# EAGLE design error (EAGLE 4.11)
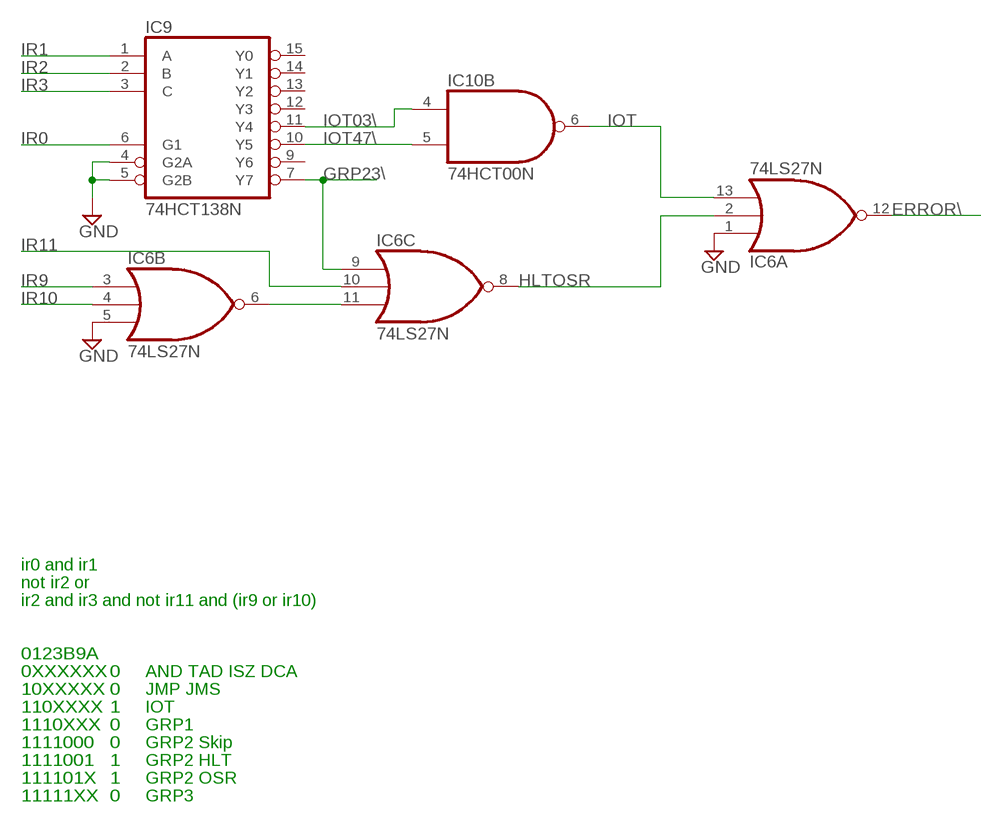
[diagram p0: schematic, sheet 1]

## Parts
IC6  74LS27N  [DIL14]
IC9  74HCT138N  [DIL16]
IC10  74HCT00N  [DIL14]

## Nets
ERROR\: IC6.12(A:O)
GND: IC6.1(A:I0) IC6.5(B:I2) IC9.4(G2A) IC9.5(G2B)
GRP23\: IC6.9(C:I0) IC9.7(Y7)
HLTOSR: IC6.2(A:I1) IC6.8(C:O)
IOT: IC6.13(A:I2) IC10.6(B:O)
IOT03\: IC9.11(Y4) IC10.4(B:I0)
IOT47\: IC9.10(Y5) IC10.5(B:I1)
IR0: IC9.6(G1)
IR1: IC9.1(A)
IR2: IC9.2(B)
IR3: IC9.3(C)
IR9: IC6.3(B:I0)
IR10: IC6.4(B:I1)
IR11: IC6.10(C:I1)
N$14: IC6.6(B:O) IC6.11(C:I2)
Unconnected: IC9.9(Y6) IC9.12(Y3) IC9.13(Y2) IC9.14(Y1) IC9.15(Y0) IC10.1(A:I0) IC10.2(A:I1) IC10.3(A:O) IC10.8(C:O) IC10.9(C:I0) IC10.10(C:I1) IC10.11(D:O) IC10.12(D:I0) IC10.13(D:I1)

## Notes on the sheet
- ir0 and ir1
- not ir2 or
- ir2 and ir3 and not ir11 and (ir9 or ir10)
- 0123B9A
- 0XXXXXX | 0 | AND TAD ISZ DCA
- 10XXXXX | 0 | JMP JMS
- 110XXXX | 1 | IOT
- 1110XXX | 0 | GRP1
- 1111000 | 0 | GRP2 Skip
- 1111001 | 1 | GRP2 HLT
- 111101X | 1 | GRP2 OSR
- 11111XX | 0 | GRP3

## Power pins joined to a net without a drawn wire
GND: IC6.7(P:GND) IC9.8(GND) IC10.7(P:GND)
VCC: IC6.14(P:VCC) IC9.16(VCC) IC10.14(P:VCC)

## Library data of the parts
IC6 = 74xx-jameco:74*27: Triple 3-input NOR gate
IC9 = 74xx-jameco:74*138: 3-line to 8-line DECODER/DEMULTIPLEXER
IC10 = 74xx-jameco:74*00: Quad 2-input NAND gate

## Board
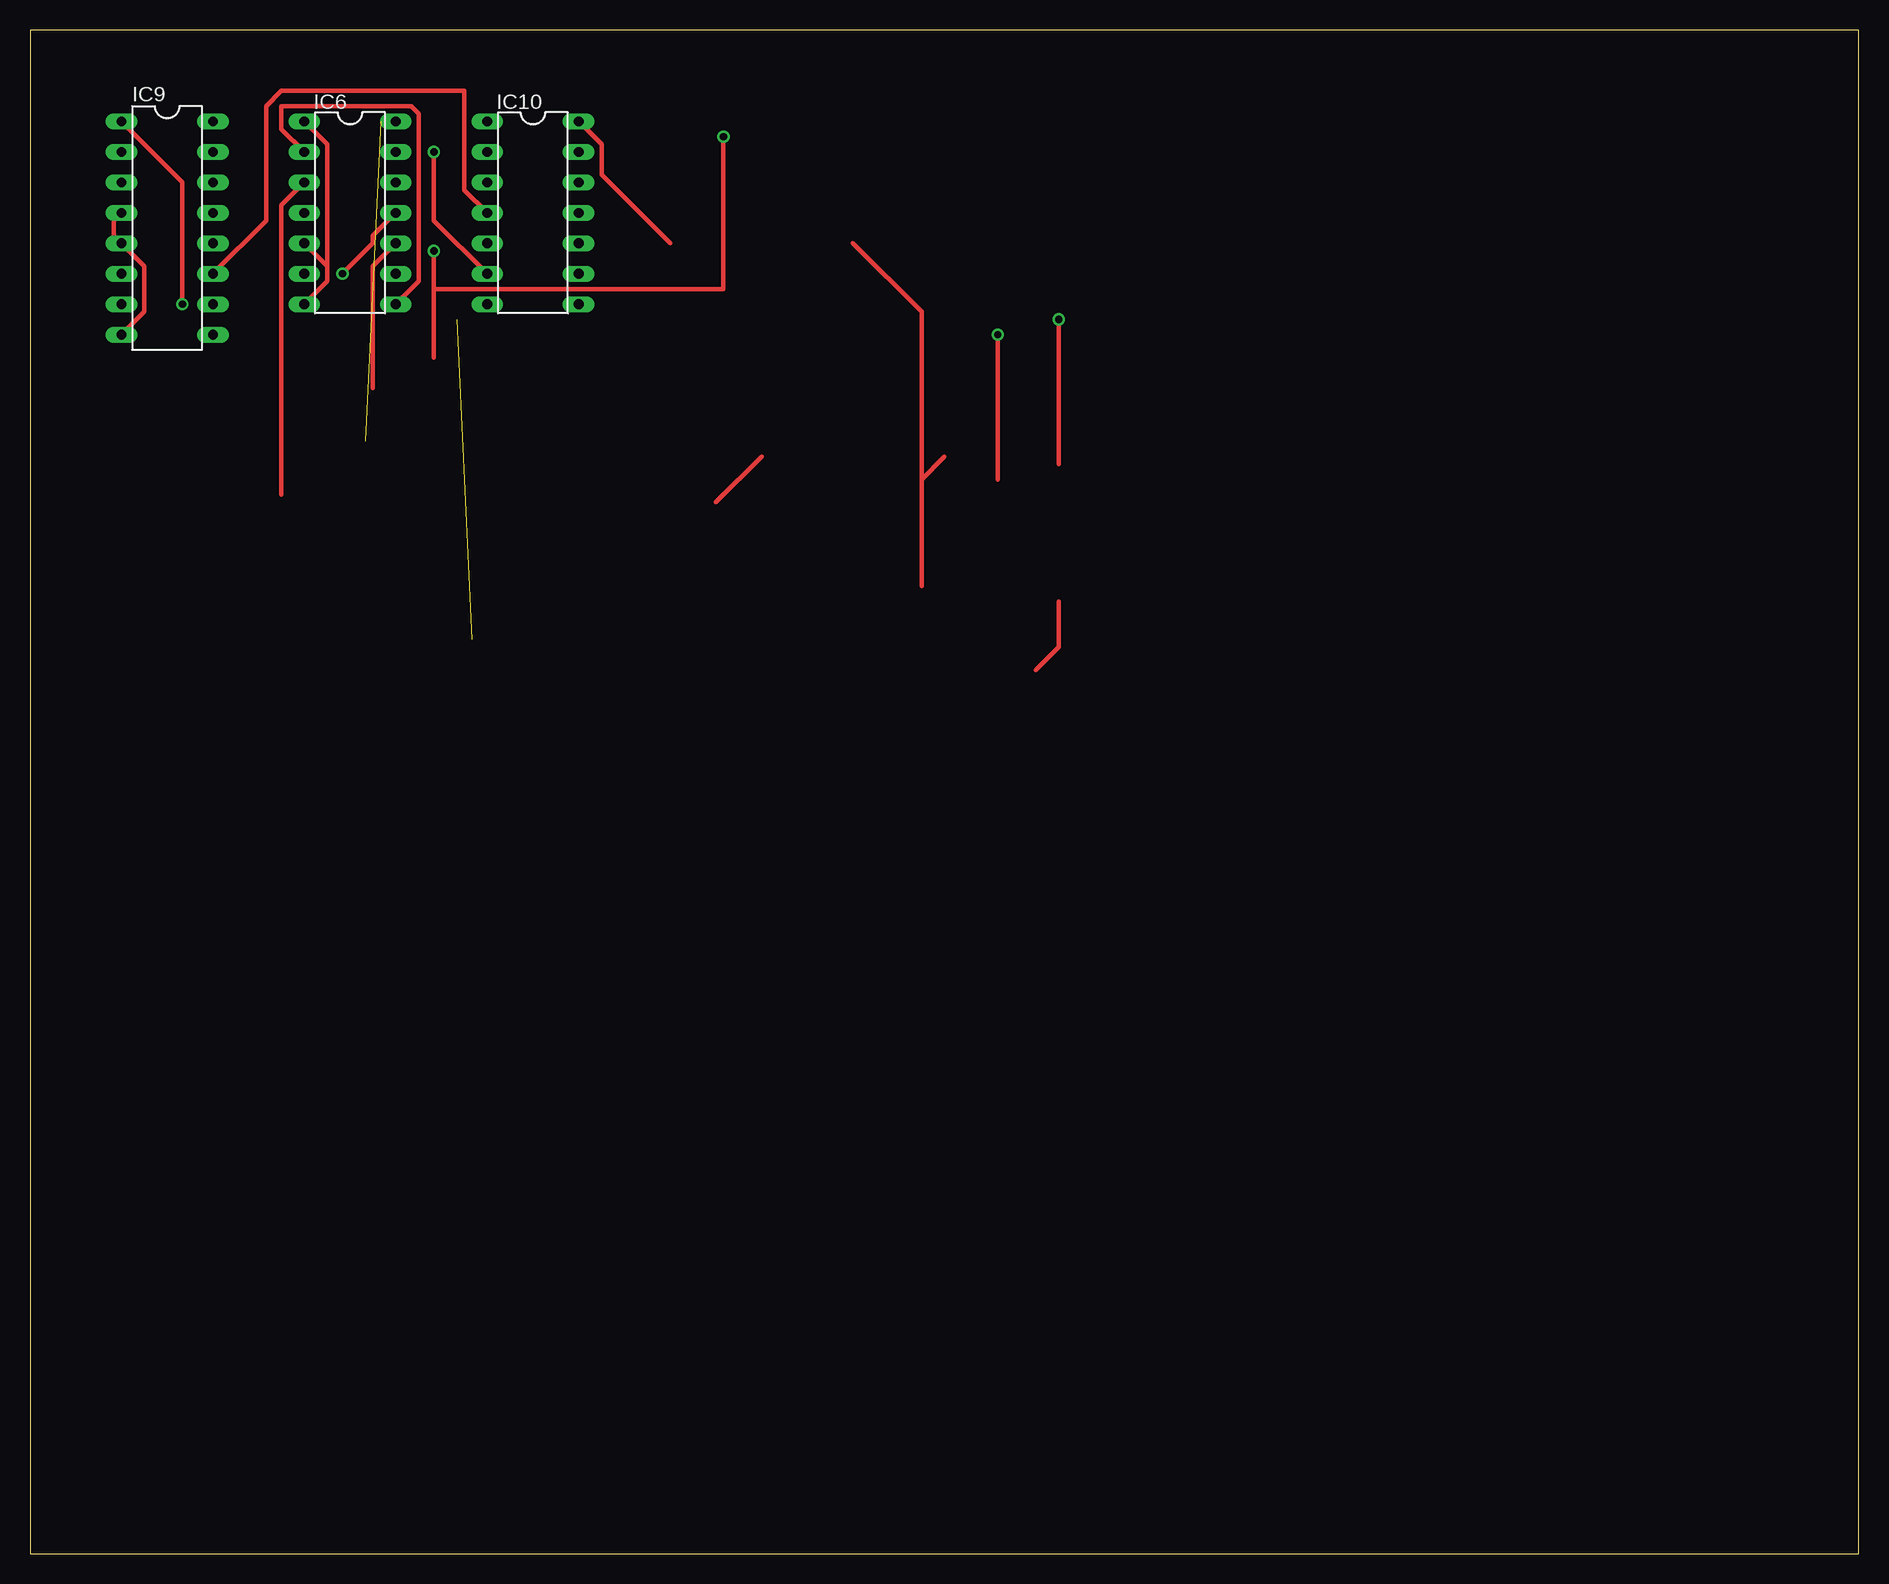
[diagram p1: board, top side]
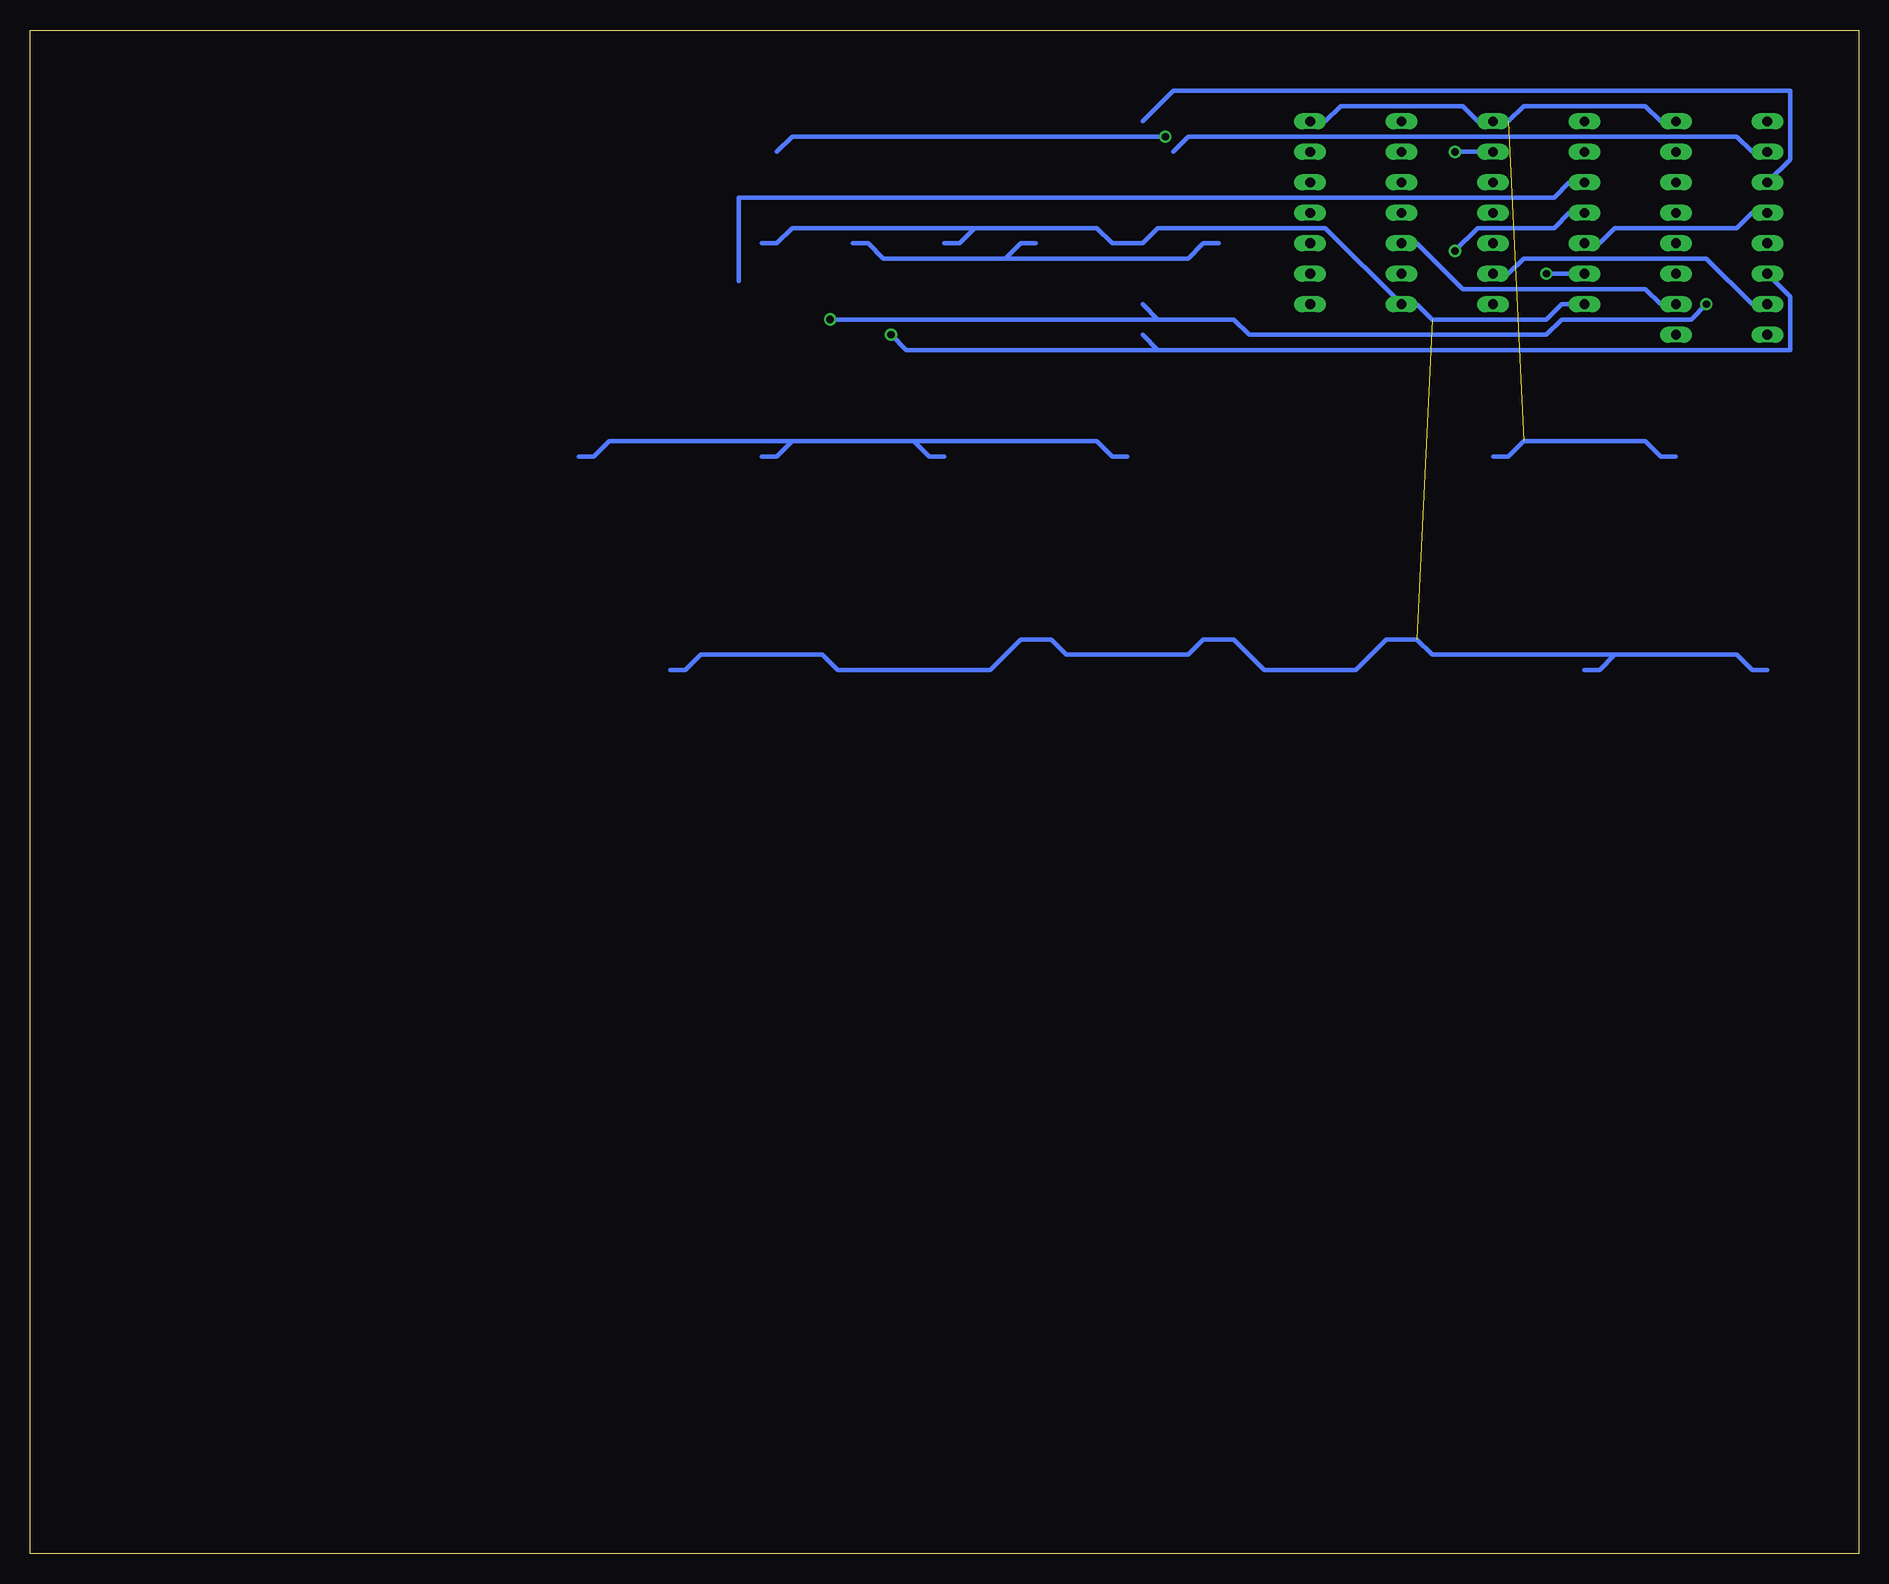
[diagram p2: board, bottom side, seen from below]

Size 152.4 x 127 mm. Coordinates in mm from the lower left corner, seen from the top.
Outline: 0,0 152.4,0 152.4,127 0,127 0,0
Copper layers (1*16): Top 0.035mm / dielectric 1.5mm / Bottom 0.035mm
Design rules "15mils": minimum track width 15mil, minimum drill 24mil, track to track 15mil, track to pad 10mil, pad to pad 10mil, via to via 10mil, smd to smd 10mil, copper to edge 25mil, drill to drill 10mil, minimum pad ring 10mil, minimum via ring 8mil, stop-mask expansion 0mil, vias tented up to drill 0mil, thermal gap 10mil

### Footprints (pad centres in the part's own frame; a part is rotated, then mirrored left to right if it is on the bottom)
DIL14 = drill 0.813 long: 1 -7.62,-3.81; 2 -5.08,-3.81; 3 -2.54,-3.81; 4 0,-3.81; 5 2.54,-3.81; 6 5.08,-3.81; 7 7.62,-3.81; 8 7.62,3.81; 9 5.08,3.81; 10 2.54,3.81; 11 0,3.81; 12 -2.54,3.81; 13 -5.08,3.81; 14 -7.62,3.81
DIL16 = drill 0.813 long: 1 -8.89,-3.81; 2 -6.35,-3.81; 3 -3.81,-3.81; 4 -1.27,-3.81; 5 1.27,-3.81; 6 3.81,-3.81; 7 6.35,-3.81; 8 8.89,-3.81; 9 8.89,3.81; 10 6.35,3.81; 11 3.81,3.81; 12 1.27,3.81; 13 -1.27,3.81; 14 -3.81,3.81; 15 -6.35,3.81; 16 -8.89,3.81

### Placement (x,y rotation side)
IC6  26.67,111.76 270 top
IC9  11.43,110.49 270 top
IC10  41.91,111.76 270 top

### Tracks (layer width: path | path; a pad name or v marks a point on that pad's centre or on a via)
GND  (2 unrouted)
  Top 0.381: 85.72,79.38 85.72,75.56 83.82,73.66 | IC9.8 9.53,103.5 9.53,107.31 IC9.5 6.99,109.86 6.99,111.12 IC9.4 | 24.77,107.31 24.77,106.05 IC6.7 | IC6.5 24.77,107.31 | 24.77,107.31 24.77,117.47 IC6.1
  Bottom 0.381: 20.32,74.93 10.16,74.93 8.89,73.66 7.62,73.66 | 20.32,74.93 21.59,73.66 22.86,73.66 | 20.32,74.93 35.56,74.93 36.83,76.2 38.1,76.2 39.37,76.2 41.91,73.66 49.53,73.66 52.07,76.2 53.34,76.2 54.61,76.2 55.88,74.93 66.04,74.93 67.31,76.2 68.58,76.2 69.85,76.2 72.39,73.66 83.82,73.66 85.09,73.66 86.36,74.93 96.52,74.93 97.79,73.66 99.06,73.66 | 73.66,110.49 63.5,110.49 62.23,109.22 60.96,109.22 59.69,109.22 58.42,110.49 44.45,110.49 IC10.7 36.83,104.14 35.56,102.87 26.04,102.87 24.77,104.14 IC6.7 | 73.66,110.49 74.93,109.22 76.2,109.22 | 73.66,110.49 88.9,110.49 90.17,109.22 91.44,109.22 | IC9.4 8.89,111.76 10.16,110.49 20.32,110.49 21.59,109.22 IC6.5
GRP23\
  Bottom 0.381: IC9.7 8.89,104.14 12.7,107.95 27.94,107.95 29.21,106.68 IC6.9
HLTOSR
  Top 0.381: IC6.8 32.38,106.05 32.38,120.02 31.75,120.65 20.95,120.65 20.95,118.75 IC6.2
IOT  (via drill 0.61)
  Top 0.381: v33.66,116.84 33.66,111.12 IC10.6
  Bottom 0.381: v33.66,116.84 IC6.13
IOT03\
  Top 0.381: IC9.11 19.68,111.12 19.68,120.65 20.95,121.92 36.2,121.92 36.2,113.67 IC10.4
IOT47\
  Bottom 0.381: IC9.10 16.51,104.14 17.78,105.41 33.02,105.41 36.83,109.22 IC10.5
IR0  (via drill 0.61)
  Top 0.381: v80.64,101.6 80.64,89.53
  Bottom 0.381: 58.42,100.33 5.71,100.33 5.71,104.78 IC9.6 | 58.42,100.33 59.69,101.6 | v80.64,101.6 79.38,100.33 58.42,100.33
IR1  (via drill 0.61)
  Top 0.381: v12.7,104.14 12.7,114.3 IC9.1 | v85.72,102.87 85.72,90.81
  Bottom 0.381: v12.7,104.14 13.97,102.87 24.77,102.87 26.04,101.6 50.8,101.6 52.07,102.87 58.42,102.87 | 58.42,102.87 59.69,104.14 | 58.42,102.87 v85.72,102.87
IR2
  Bottom 0.381: 57.15,116.84 55.88,118.11 10.16,118.11 8.89,116.84 IC9.2
IR3
  Bottom 0.381: 59.69,119.38 57.15,121.92 5.71,121.92 5.71,116.2 IC9.3
IR9
  Top 0.381: 20.95,88.27 20.95,112.39 IC6.3
  Bottom 0.381: 93.34,106.05 93.34,113.03 25.4,113.03 24.13,114.3 IC6.3
IR10  (via drill 0.61)
  Top 0.381: 33.66,105.41 v33.66,108.58 | 33.66,99.69 33.66,105.41 | 33.66,105.41 57.78,105.41 v57.78,118.11
  Bottom 0.381: v33.66,108.58 31.75,110.49 25.4,110.49 24.13,111.76 IC6.4 | v57.78,118.11 88.9,118.11 90.17,116.84
IR11
  Top 0.381: 28.57,97.16 28.57,107.31 IC6.10
N$14  (via drill 0.61)
  Top 0.381: v26.04,106.68 28.57,109.22 28.57,109.86 IC6.11
  Bottom 0.381: IC6.6 v26.04,106.68
VCC  (5 unrouted)
  Top 0.381: 57.15,87.63 60.96,91.44 | 53.34,109.22 47.62,114.94 47.62,117.47 IC10.14 | 74.3,80.64 74.3,89.53 | 74.3,89.53 76.2,91.44 | 74.3,89.53 74.3,103.5 68.58,109.22
  Bottom 0.381: 15.24,91.44 16.51,91.44 17.78,92.71 27.94,92.71 29.21,91.44 30.48,91.44 | IC9.16 16.51,119.38 17.78,120.65 27.94,120.65 29.21,119.38 IC6.14 31.75,119.38 33.02,120.65 43.18,120.65 44.45,119.38 IC10.14 | 88.9,92.71 90.17,91.44 91.44,91.44 | 78.74,92.71 88.9,92.71 | 78.74,92.71 77.47,91.44 76.2,91.44 | 88.9,92.71 104.14,92.71 105.41,91.44 106.68,91.44 | 71.12,107.95 81.28,107.95 82.55,109.22 83.82,109.22 | 71.12,107.95 69.85,109.22 68.58,109.22 | 71.12,107.95 55.88,107.95 54.61,109.22 53.34,109.22 | 78.74,92.71 63.5,92.71 62.23,91.44 60.96,91.44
